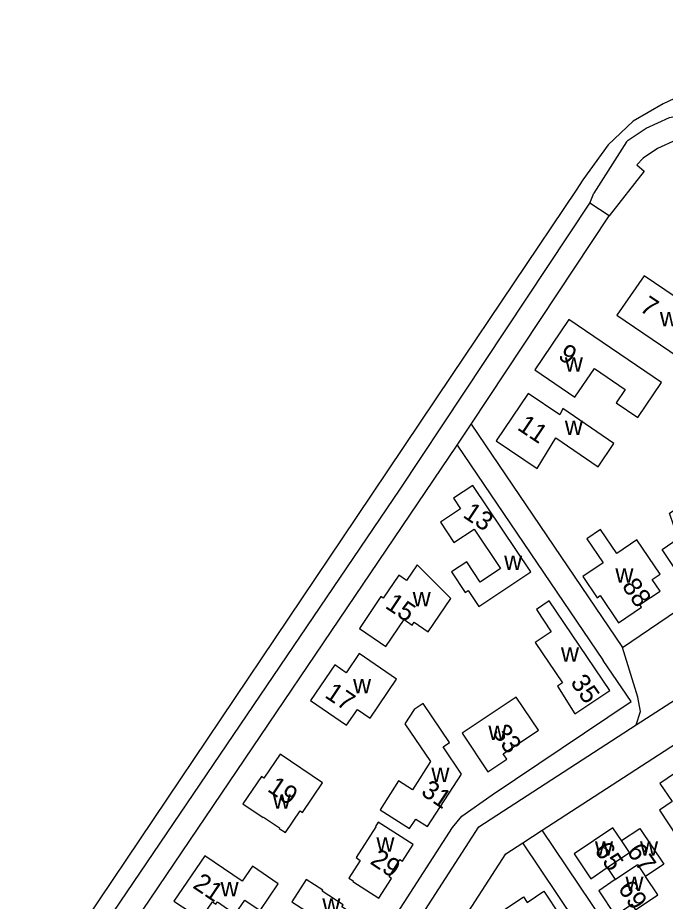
# Model space of a CAD drawing. Extents: x 158356 to 159894, y 383831 to 385260.
# Drawn here: x 158887.4 to 159026.2, y 384774.6 to 384964 of the extents above; entities that cross this region are included whole.
import ezdxf

# ---------------------------------------------------------------- set-up
doc = ezdxf.new("R2010")
doc.units = 0
for name, color, linetype in [('BLT_Basislijn', 7, 'Continuous'), ('BLT_Bebouwing', 7, 'Continuous'), ('BLT_Centroide', 7, 'Continuous'), ('BLT_Huisnummer', 7, 'Continuous'), ('BLT_Onderverdeling_panden', 7, 'Continuous'), ('BLT_Straatnaam', 7, 'Continuous'), ('BLT_Vlakafsluiter', 7, 'Continuous')]:
    doc.layers.add(name, color=color, linetype=linetype)

msp = doc.modelspace()

# ---------------------------------------------------------------- linework, layer by layer
at = {"layer": 'BLT_Basislijn'}
for p, q in [((159017.95, 384937.38), (159010.93, 384926.39)), ((159008.59, 384929.21), (159007.12, 384927.02)), ((159007.12, 384927.02), (158980.42, 384887.32)), ((159014.23, 384921.49), (159010.07, 384924.25)), ((158984.59, 384876.83), (159014.23, 384921.49)), ((158980.42, 384887.32), (158959.93, 384856.85)), ((158981.6, 384872.33), (158984.59, 384876.83)), ((158984.59, 384876.83), (159017.09, 384829.01)), ((158892.72, 384740.96), (158981.6, 384872.33)), ((158981.6, 384872.33), (159012.95, 384826.2)), ((158889.73, 384745.46), (158969.38, 384862.96)), ((159017.09, 384829.01), (159038.59, 384843.63)), ((158995.67, 384787.14), (158999.87, 384789.85)), ((159016.34, 384765.35), (158999.87, 384789.85)), ((159014.17, 384759.62), (158995.67, 384787.14))]:
    msp.add_line(p, q, dxfattribs=at)
for points in [[(159054.25, 384963.98), (159046.92, 384957.01), (159037.1, 384950.83), (159025.81, 384945.55), (159019.32, 384941.8), (159013.99, 384936.74), (159008.59, 384929.21)], [(159017.95, 384937.38), (159018.31, 384937.75), (159022.13, 384940.3), (159027.14, 384942.6), (159031.42, 384943.42), (159039.22, 384944), (159043.65, 384945.1), (159047.13, 384946.18), (159047.75, 384946.63), (159051.81, 384950.01), (159055.71, 384954.22)], [(159056.81, 384948.05), (159055.26, 384946.38), (159050.81, 384942.67), (159049.39, 384941.65), (159044.99, 384940.28), (159040.01, 384939.05), (159032.08, 384938.45), (159028.67, 384937.81), (159024.58, 384935.92), (159021.52, 384933.88), (159020.13, 384932.46), (159021.69, 384931.08), (159014.23, 384921.49)], [(158969.38, 384862.96), (158983.03, 384883.52), (159010.07, 384924.25), (159010.93, 384926.39)], [(158959.93, 384856.85), (158887.39, 384748.99)], [(159020.01, 384812.41), (159020.93, 384815.29), (159020.32, 384818.34), (159017.09, 384829.01)], [(158921.14, 384698.19), (158980.6, 384790.41), (158982.62, 384792.82), (158989.15, 384797.43), (159018.93, 384817.4), (159012.95, 384826.2)], [(158934.83, 384710.79), (158986.23, 384790.56), (159020.01, 384812.41)], [(158999.87, 384789.85), (159031.07, 384810.03), (159034.22, 384811.25), (159036.9, 384811.25), (159038.99, 384810.81), (159040.4, 384809.78)], [(158967.99, 384747.49), (158992.02, 384784.77), (158995.67, 384787.14)]]:
    msp.add_lwpolyline(points, dxfattribs=at)
at = {"layer": 'BLT_Bebouwing'}
msp.add_line((159013.8, 384781.82), (159015.52, 384779.25), dxfattribs=at)
for points in [[(159021.69, 384908.66), (159015.88, 384900.19), (159029, 384891.29), (159034.76, 384899.79)], [(159005.59, 384899.26), (158998.26, 384888.48), (159006.87, 384882.64), (159011.04, 384888.77), (159017.65, 384884.29), (159015.73, 384881.45), (159020.37, 384878.3), (159025.42, 384885.77)], [(158996.87, 384883.42), (158989.98, 384873.32), (158998.74, 384867.38), (159002.76, 384873.91), (159011.83, 384867.74), (159015.22, 384872.74), (159004.3, 384880.2), (159003.6, 384878.85)], [(158984.97, 384863.71), (158980.86, 384860.97), (158982.33, 384858.73), (158978.02, 384855.84), (158980.93, 384851.47), (158985.26, 384854.36), (158990.9, 384845.93), (158986.55, 384843.01), (158983.67, 384847.34), (158980.43, 384845.18), (158983.34, 384840.8), (158983.98, 384841.23), (158986.29, 384837.78), (158997.38, 384845.23)], [(159027.16, 384857.76), (159032.2, 384861.14), (159037.98, 384852.52), (159035.57, 384850.9), (159037.16, 384848.54), (159034.56, 384846.79), (159035.95, 384844.71), (159031.23, 384841.54), (159025.55, 384850), (159029.03, 384852.33)], [(159015.83, 384849.11), (159012.35, 384854.26), (159009.43, 384852.28), (159012.91, 384847.13), (159008.57, 384844.19), (159011.63, 384839.67), (159012.27, 384840.11), (159016.2, 384834.31), (159021.12, 384837.64), (159020.76, 384838.18), (159025.12, 384841.1), (159023.45, 384843.59), (159025.11, 384844.69), (159020.16, 384852.04)], [(158973.07, 384846.72), (158970.76, 384843.36), (158969.11, 384844.48), (158965.77, 384839.58), (158965.28, 384839.91), (158960.65, 384833.09), (158966.33, 384829.22), (158970.25, 384834.98), (158971.97, 384833.81), (158972.4, 384834.43), (158975.41, 384832.37), (158980.26, 384839.5)], [(159001.32, 384838.96), (158998.6, 384837.13), (159001.8, 384832.36), (158998.35, 384830.07), (159004.18, 384821.4), (159003.09, 384820.67), (159006.85, 384814.75), (159014.35, 384819.76)], [(158960.59, 384827.68), (158957.82, 384823.59), (158955.39, 384825.27), (158950.15, 384817.66), (158957.91, 384812.31), (158960.24, 384815.7), (158962.93, 384813.84), (158968.64, 384822.2)], [(158994.26, 384818.38), (158982.66, 384810.63), (158988.22, 384802.34), (158992.28, 384805.05), (158991.5, 384806.23), (158999.04, 384811.27)], [(158975.27, 384790.59), (158982.53, 384801.83), (158978.6, 384807.71), (158979.97, 384808.63), (158974.35, 384816.98), (158972.39, 384815.67), (158970.42, 384812.64), (158975.88, 384804.53), (158972.02, 384798.51), (158969.07, 384800.4), (158965.11, 384794.21), (158971.41, 384790.17), (158972.75, 384792.23)], [(158939.67, 384801.34), (158935.68, 384795.48), (158940.05, 384792.53), (158940.11, 384792.63), (158943.53, 384790.32), (158943.46, 384790.22), (158944.8, 384789.31), (158947.96, 384793.96), (158948.46, 384793.62), (158952.76, 384799.95), (158943.65, 384806.13), (158940.18, 384800.99)], [(158964.7, 384791.53), (158964.09, 384790.62), (158964.18, 384790.56), (158959.95, 384783.96), (158960.85, 384783.35), (158958.41, 384779.56), (158959.33, 384778.97), (158959.28, 384778.86), (158964.79, 384775.27), (158967.52, 384779.46), (158967, 384779.81), (158969.35, 384783.53), (158969.88, 384783.19), (158972.16, 384786.74)], [(158927.51, 384784.36), (158920.86, 384774.63), (158926.64, 384770.81), (158929.15, 384774.49), (158929.9, 384773.97), (158930.23, 384774.45), (158934.02, 384771.86), (158936.06, 384774.85), (158939.35, 384772.61), (158943.25, 384778.32), (158937.72, 384782.1), (158935.52, 384778.89)], [(158949.27, 384779.28), (158946.17, 384774.48), (158954.14, 384769.33), (158951.16, 384764.68), (158950.57, 384765.04), (158947.91, 384760.98), (158952.83, 384757.8), (158955.93, 384762.58), (158956.93, 384761.93), (158959.46, 384765.87), (158962.14, 384770.01), (158956.92, 384773.38), (158957.19, 384773.8), (158952.66, 384776.73), (158952.83, 384776.98)]]:
    msp.add_lwpolyline(points, close=True, dxfattribs=at)
for points in [[(159035.37, 384801.1), (159032.72, 384805.03), (159025.07, 384799.87), (159027.7, 384795.96)], [(159027.7, 384795.96), (159024.98, 384794.14), (159030.53, 384785.8), (159035.81, 384789.34), (159033.44, 384792.91)], [(159016.86, 384787.59), (159015.02, 384790.32), (159006.72, 384784.74), (159010.26, 384779.42), (159013.8, 384781.82)], [(159016.86, 384787.59), (159020.78, 384790.23), (159025.95, 384782.55), (159022.01, 384779.91)], [(159015.52, 384779.25), (159011.97, 384776.85), (159015.48, 384771.57), (159019.09, 384773.99), (159019.88, 384772.79), (159024.63, 384776), (159022.01, 384779.91)], [(158993.72, 384768.43), (158991.06, 384772.36), (158995.81, 384775.53), (158996.61, 384774.35), (159000.16, 384776.73), (159003.69, 384771.48), (159000.12, 384769.08)]]:
    msp.add_lwpolyline(points, dxfattribs=at)
at = {"layer": 'BLT_Onderverdeling_panden'}
for points in [[(159013.8, 384781.82), (159018.58, 384785.05), (159016.86, 384787.59)], [(159015.52, 384779.25), (159020.3, 384782.48), (159022.01, 384779.91)]]:
    msp.add_lwpolyline(points, dxfattribs=at)
at = {"layer": 'BLT_Vlakafsluiter'}
msp.add_line((159020.01, 384812.41), (159031.08, 384819.56), dxfattribs=at)

# ---------------------------------------------------------------- texts
at = {"layer": 'BLT_Centroide'}
for p in [(159025.07, 384897.83), (159004.7, 384888.1), (159004.7, 384874.53), (158991.68, 384845.63), (159015.54, 384842.86), (158972.08, 384837.81), (159003.87, 384825.94), (158959.3, 384819.19), (158988.31, 384809.17), (158976.09, 384800.14), (158942.08, 384794.43), (158964.3, 384785.24), (159011.16, 384784.36), (159020.82, 384784.36), (159017.7, 384776.81), (158930.89, 384775.65), (158952.71, 384772.13)]:
    msp.add_text('w', height=4, dxfattribs=at).set_placement(p)
at = {"layer": 'BLT_Huisnummer'}
for s, rotation, p in [('7', 326.218, (159020.53, 384901.29)), ('9', 326.218, (159003.03, 384891.05)), ('11', 326.218, (158994.29, 384875.83)), ('13', 326.218, (158982.63, 384857.06)), ('88', 304.8063, (159016.81, 384842.14)), ('15', 326.218, (158965.96, 384837.6)), ('35', 304.8063, (159005.77, 384821.5)), ('17', 326.218, (158953.01, 384818.44)), ('33', 304.8063, (158989.02, 384810.81)), ('19', 326.218, (158940.72, 384798.32)), ('31', 326.218, (158973.64, 384797.56)), ('29', 326.218, (158962.73, 384782.79)), ('65', 304.8063, (159010.88, 384785.59)), ('67', 304.8063, (159017.85, 384785.3)), ('21', 326.218, (158924.72, 384777.61)), ('69', 304.8063, (159015.95, 384777.33))]:
    msp.add_text(s, height=4, rotation=rotation, dxfattribs=at).set_placement(p)
at = {"layer": 'BLT_Straatnaam'}
msp.add_text('SCHADUWMASKERSTRAAT', height=5, rotation=33.8882, dxfattribs=at).set_placement((158979.65, 384728.63))

doc.saveas('drawing.dxf')
